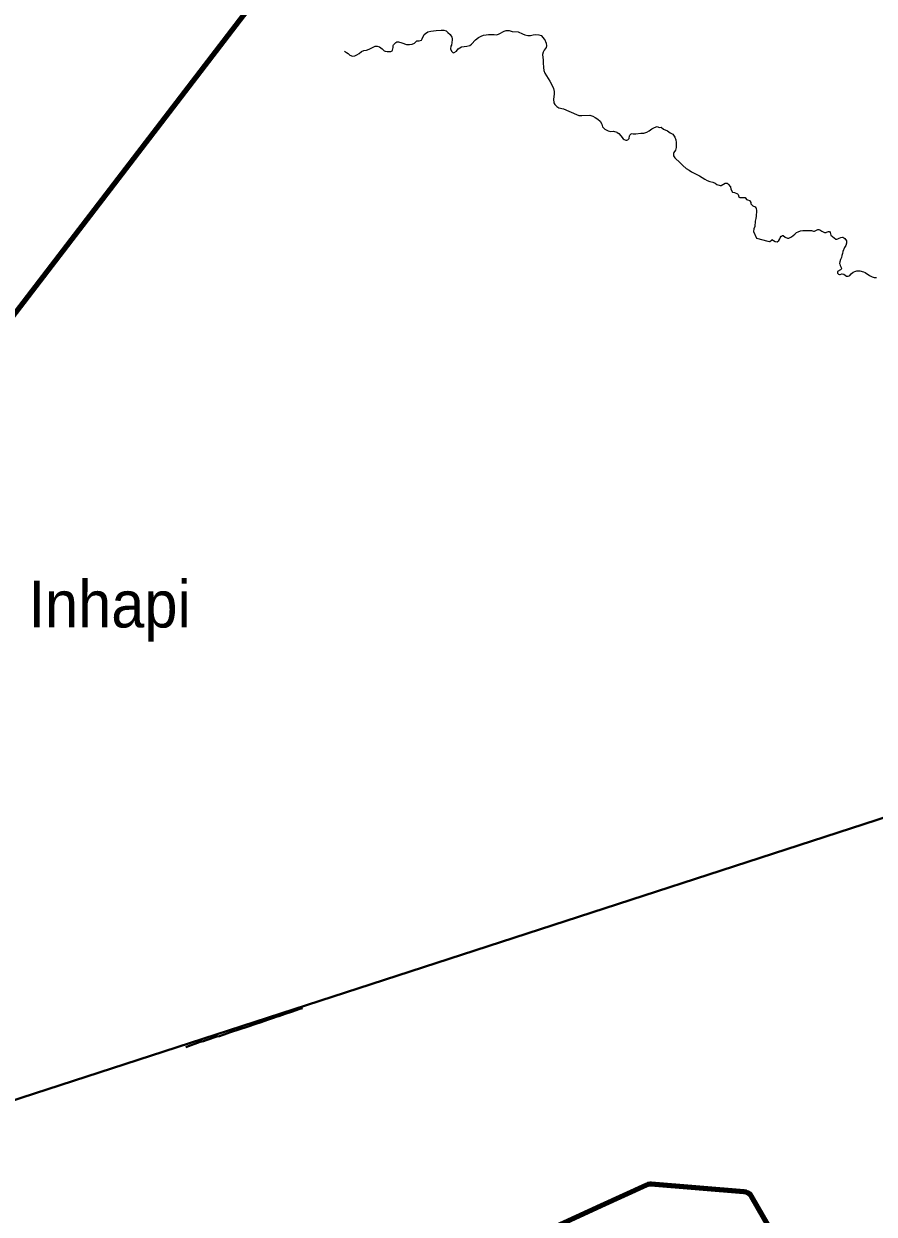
# Model space of a CAD drawing. Extents: x 553962 to 842807, y 8883888 to 9032388.
# Drawn here: x 637499 to 646568, y 8973850 to 8986538 of the extents above; entities that cross this region are included whole.
import ezdxf

# ---------------------------------------------------------------- set-up
doc = ezdxf.new("R2010")
doc.units = 0
doc.header["$LTSCALE"] = 200
doc.linetypes.add('DOT_DASHED', pattern=[7.7, 5, -1.2, 0.3, -1.2])
for name, color, linetype, lineweight in [('12', 7, 'Continuous', 25), ('24', 7, 'Continuous', 25), ('7', 7, 'Continuous', 90), ('9', 7, 'Continuous', 90)]:
    doc.layers.add(name, color=color, linetype=linetype, lineweight=lineweight)
doc.layers.add('41', color=7, linetype='Continuous')

msp = doc.modelspace()

# ---------------------------------------------------------------- linework, layer by layer
at = {"layer": '12', "lineweight": 40}
msp.add_line((636526.5, 8974783.6), (662912, 8983353), dxfattribs=at)
for points in [[(640472.4, 8976046.8), (640441.5, 8976036.8), (640353.5, 8976006.1), (640287.6, 8975985.5), (640218.7, 8975961.9), (640200.9, 8975957.3), (640150.5, 8975938.5), (640099.3, 8975922.4), (640029.6, 8975897.5), (639963, 8975876.6), (639893.2, 8975851.7), (639703, 8975789.1)], [(639703, 8975789.1), (639664.1, 8975776.3), (639645.5, 8975769.1), (639623.8, 8975762.9), (639586.7, 8975748.7), (639556.7, 8975741.9), (639455.8, 8975707.4), (639444.1, 8975705), (639415.3, 8975694.5), (639380.3, 8975685.2), (639226.1, 8975631.6)]]:
    msp.add_lwpolyline(points, dxfattribs=at)
at = {"layer": '24'}
for points in [[(640918.4, 8986246.1), (640939.3, 8986233.2), (640958.6, 8986220.4), (640974.7, 8986202.7), (641005.2, 8986193), (641027.8, 8986197.9), (641050.3, 8986207.5), (641076.6, 8986220.6), (641099, 8986243.2), (641125.1, 8986253.3), (641153.7, 8986258.2), (641180.7, 8986267.4), (641247.9, 8986299.8), (641252.4, 8986300.8), (641265.9, 8986300.5), (641292.7, 8986293.1), (641322, 8986270.3), (641342.1, 8986250.7), (641354.3, 8986244.5), (641374.6, 8986241.8), (641397.6, 8986241), (641413.7, 8986242.2), (641425.8, 8986248.1), (641430.8, 8986256.1), (641439.1, 8986285), (641439.6, 8986307.4), (641442.2, 8986313.7), (641465.6, 8986337.5), (641476.7, 8986343.9), (641494.1, 8986344.5), (641529.5, 8986336.6), (641579.3, 8986318.8), (641613.9, 8986317), (641641.7, 8986320.3), (641665.2, 8986332.1), (641689, 8986354.9), (641716.6, 8986356.6), (641739.9, 8986363.2), (641749.1, 8986376.7), (641769.3, 8986422.7), (641783.8, 8986436.1), (641809.2, 8986452.8), (641838.7, 8986459.2), (641897.4, 8986468), (641950.8, 8986470.9), (641977.8, 8986468.7), (642001.6, 8986462.8), (642022.7, 8986446.3), (642045.1, 8986422.7), (642062.2, 8986395.1), (642067.7, 8986379.8), (642067.4, 8986365.3), (642059.7, 8986311), (642053.8, 8986298.9), (642051, 8986272.1), (642060.4, 8986246.1), (642074.6, 8986231), (642083.8, 8986229.3), (642088.7, 8986230.9), (642112.8, 8986245.9), (642131.7, 8986271.2), (642167.5, 8986292.7), (642223.9, 8986298.8), (642254.2, 8986307.8), (642273.7, 8986320.8), (642314.6, 8986365.6), (642348.1, 8986390.6), (642375.5, 8986406.4), (642402.4, 8986416.7), (642429.4, 8986421.7), (642455.4, 8986424.7), (642486, 8986422.9), (642515, 8986422.7), (642542.8, 8986419), (642568.2, 8986430.8), (642620.2, 8986459.8), (642643.2, 8986464.7), (642676.8, 8986465.5), (642708.6, 8986455), (642772.3, 8986450.6), (642818.2, 8986429.7), (642843.8, 8986419.7), (642873.8, 8986412.4), (642902.4, 8986413.3), (642931.2, 8986419.8), (642961.1, 8986424.8), (642990.2, 8986421.6), (643016.2, 8986411.7), (643039.1, 8986389.9), (643046.4, 8986376.2), (643052.1, 8986372.3), (643069.2, 8986330.8), (643073.5, 8986303.9), (643070.2, 8986285), (643047.5, 8986257.6), (643036.1, 8986236.1), (643032.3, 8986209.7), (643037.2, 8986151.9), (643037.4, 8986120.1), (643040.2, 8986072.2), (643045.5, 8986041.5)], [(643045.5, 8986041.5), (643045.5, 8986041.5), (643056, 8986011.1), (643071.6, 8985984.1), (643109.4, 8985927.6), (643137, 8985874.4), (643147.9, 8985846.7), (643153.9, 8985815.2), (643153.8, 8985788.4), (643147.7, 8985733.6), (643151.8, 8985695.4), (643163.7, 8985678), (643182.5, 8985656.3), (643204.1, 8985642.6), (643255.2, 8985632.2), (643391.8, 8985570.3), (643419.6, 8985560.6), (643448.3, 8985559.2), (643535.1, 8985564.4), (643566.8, 8985554.4), (643593.8, 8985539.8), (643620, 8985522.8), (643645.8, 8985498.4), (643661.8, 8985469), (643671.2, 8985440.6), (643696.1, 8985416.2), (643730.8, 8985396.7), (643760.5, 8985389.3), (643787.3, 8985391.9), (643824.7, 8985383.8), (643827.6, 8985378.5), (643844.2, 8985367.4), (643865.5, 8985345.4), (643891.9, 8985312.7), (643902.2, 8985304.6), (643918.1, 8985298.3), (643931.2, 8985298.1), (643942, 8985300.2), (643956, 8985315.2), (643958.1, 8985343.4), (643962.6, 8985351.1), (643974.6, 8985365.4), (643986.6, 8985368.4), (643998.1, 8985366.4), (644024.1, 8985364.5), (644080, 8985371.7), (644110.9, 8985373), (644143.4, 8985382.5), (644168.5, 8985396.6), (644196.1, 8985417.2), (644224.2, 8985431.8), (644254, 8985444.8), (644273.9, 8985433.2), (644296.8, 8985435.6), (644322.2, 8985414.2), (644363.5, 8985395.3), (644391.1, 8985376.3), (644419.5, 8985362.5), (644442.3, 8985331.1), (644453.3, 8985302.5), (644457.5, 8985272.5), (644457.4, 8985247.7), (644454.2, 8985219.9), (644448.7, 8985192.2), (644431.3, 8985165), (644427.1, 8985155.8), (644427.3, 8985131.1), (644442.3, 8985109.9), (644498.8, 8985056.6), (644525.5, 8985029), (644563, 8984997.2), (644593.4, 8984976), (644619.6, 8984960.8), (644704.7, 8984916.9), (644762.1, 8984880.9), (644788.2, 8984867.8), (644814.3, 8984857.8), (644846.8, 8984850.4), (644871.5, 8984838.7), (644888.1, 8984823.5), (644924.3, 8984813.9), (644936.7, 8984813.3), (644980.1, 8984838.3), (644995.5, 8984839.8), (644999.2, 8984838.9), (645011.4, 8984829.6), (645036.6, 8984800.8), (645040, 8984774.7), (645055.3, 8984741.8), (645079.3, 8984738.2), (645111, 8984727.2), (645116.6, 8984716.9), (645122.7, 8984692.8), (645125.9, 8984690.1), (645134.7, 8984687.1), (645179, 8984687.9), (645191.9, 8984684.7), (645204.7, 8984665), (645215.6, 8984660.4), (645240.1, 8984653.1), (645246.2, 8984645.1)], [(645246.2, 8984645.1), (645252, 8984633.7), (645252, 8984633.7), (645252.8, 8984617.9), (645254.9, 8984614.1), (645273, 8984596.3), (645297.8, 8984587.5), (645307.1, 8984577.2), (645309.6, 8984572.6), (645313.5, 8984545.7), (645310.3, 8984489.1), (645306.1, 8984462.2), (645298.7, 8984433.5), (645293.2, 8984378.7), (645284.9, 8984350.8), (645279.8, 8984323.9), (645312.4, 8984251.8), (645435.1, 8984220.4), (645450.8, 8984217.4), (645454.7, 8984218.6), (645473, 8984232.8), (645474.4, 8984237.7), (645513, 8984217.7), (645534.3, 8984215.3), (645552.1, 8984228.2), (645561.4, 8984244.2), (645563.4, 8984257.6), (645571, 8984266.9), (645573.8, 8984274.1), (645582.1, 8984275.2), (645588.9, 8984280.3), (645595.8, 8984280.6), (645617.2, 8984264.5), (645643.7, 8984251.2), (645657.8, 8984251.3), (645685.7, 8984265.8), (645720.8, 8984294.7), (645739.3, 8984311.6), (645757.9, 8984321.9), (645781.4, 8984331.5), (645806.7, 8984335.8), (645852, 8984333.8), (645898.3, 8984333.7), (645921.8, 8984328.7), (645932, 8984328.5), (645966, 8984344.7), (645976.9, 8984346.4), (645987.8, 8984340.9), (646010.2, 8984326), (646036.9, 8984314.5), (646055.1, 8984312.7), (646060.6, 8984315.8), (646079.4, 8984322.4), (646090.5, 8984322.5), (646097, 8984312.2), (646105.3, 8984283.1), (646157.1, 8984243.2), (646170.2, 8984242.8), (646179.3, 8984244.7), (646193.2, 8984252.7), (646210.9, 8984260.5), (646231.3, 8984263.8), (646234.4, 8984263.1), (646256, 8984249.2), (646271.1, 8984222.9), (646271.2, 8984198.1), (646264.8, 8984175), (646256.7, 8984163.4), (646252.5, 8984152.3), (646232.4, 8984111.9), (646228.6, 8984089.8), (646221.2, 8984067.5), (646217.8, 8984047), (646208.5, 8984025.5), (646201.6, 8984002.4), (646197.2, 8983982.5), (646199.9, 8983977.5), (646203.5, 8983960.5), (646214.4, 8983938.6), (646218.5, 8983926.6), (646208.4, 8983916.5), (646177.6, 8983897.5), (646174.8, 8983879.2), (646187.6, 8983870.2), (646196.7, 8983867.3), (646206, 8983867.2), (646221.1, 8983872.7), (646226.9, 8983872.9), (646242.3, 8983868.7), (646272.1, 8983849.4), (646291.4, 8983848.2), (646301.4, 8983851.2), (646309, 8983856.7), (646323, 8983874.5), (646341.7, 8983889.2), (646361.2, 8983898), (646382.2, 8983904.2), (646413.2, 8983905.6), (646451.9, 8983895.7), (646472.7, 8983885.2), (646519.1, 8983855.8)], [(646519.1, 8983855.8), (646546.1, 8983841.4), (646567, 8983833.1), (646567, 8983833.1), (646591.3, 8983832)]]:
    msp.add_lwpolyline(points, dxfattribs=at)
at = {"layer": '7'}
msp.add_lwpolyline([(641465.4, 8972935.3), (643655.4, 8973941), (644139.1, 8974163.2), (644158, 8974169.6), (644177.8, 8974172.2), (644189.1, 8974171.9), (645177.9, 8974090.8), (645197.5, 8974087.2), (645216, 8974079.7), (645232.7, 8974068.7), (645246.9, 8974054.7), (645256.3, 8974041), (646352.5, 8972136.8)], dxfattribs=at)
at = {"layer": '7', "linetype": 'DOT_DASHED'}
msp.add_lwpolyline([(641465.4, 8972935.3), (643655.4, 8973941), (644139.1, 8974163.2), (644158, 8974169.6), (644177.8, 8974172.2), (644189.1, 8974171.9), (645177.9, 8974090.8), (645197.5, 8974087.2), (645216, 8974079.7), (645232.7, 8974068.7), (645246.9, 8974054.7), (645256.3, 8974041), (646352.5, 8972136.8)], dxfattribs=at)
at = {"layer": '9'}
msp.add_lwpolyline([(635350.7, 8977923.9), (636116.8, 8981777.4), (642228, 8989744.8), (647160.3, 8990514), (649828, 8995545.6), (655722.5, 9001435.5), (661506.7, 9009120.3)], dxfattribs=at)

# ---------------------------------------------------------------- texts
at = {"layer": '41', "width": 0.95}
msp.add_text('Inhapi', height=500, dxfattribs=at).set_placement((637549, 8980103.2))

doc.saveas('drawing.dxf')
